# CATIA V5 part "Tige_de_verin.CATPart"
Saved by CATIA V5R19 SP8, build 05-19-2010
Part number: Tige de verin
Revision: ANY
Definition: UNKNOWN
Nomenclature: Tige de vérin
Source: Unknown
Bounding box of the stored display mesh (mm): x -3 to 3, y -3 to 3, z 0 to 150
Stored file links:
  D:\Documents\1_Travail\1 - ac-limoges.fr\ac-limoges.fr\Emmanuel Maynard - STI2D_Turgot\2 -2I2D\3_SEQUENCE_Serre_Connectée\Dossier technique_SERRE\Maquettes_CATIA\Vérin_Thermodynamique\Tige_de_verin.CATPart
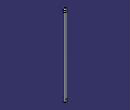
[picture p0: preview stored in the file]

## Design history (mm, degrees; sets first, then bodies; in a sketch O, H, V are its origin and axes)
Body1 "NONE" (main body)
  Solid1: solid without history
  Split1: SplitPlane face of Solid1
  Sketch1 on face of Split1, origin (0, 0, 145), H (1, 0, 0), V (0, 1, 0)
    projected circle E1 centre (0, 0) radius 3 from face of Split1
  Pad1: profile Sketch1, direction (0, 0, 1), length 5
  Fillet1: radius 1.5, on edge [face of Pad1 from Sketch1.E1 | end face of Pad1]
